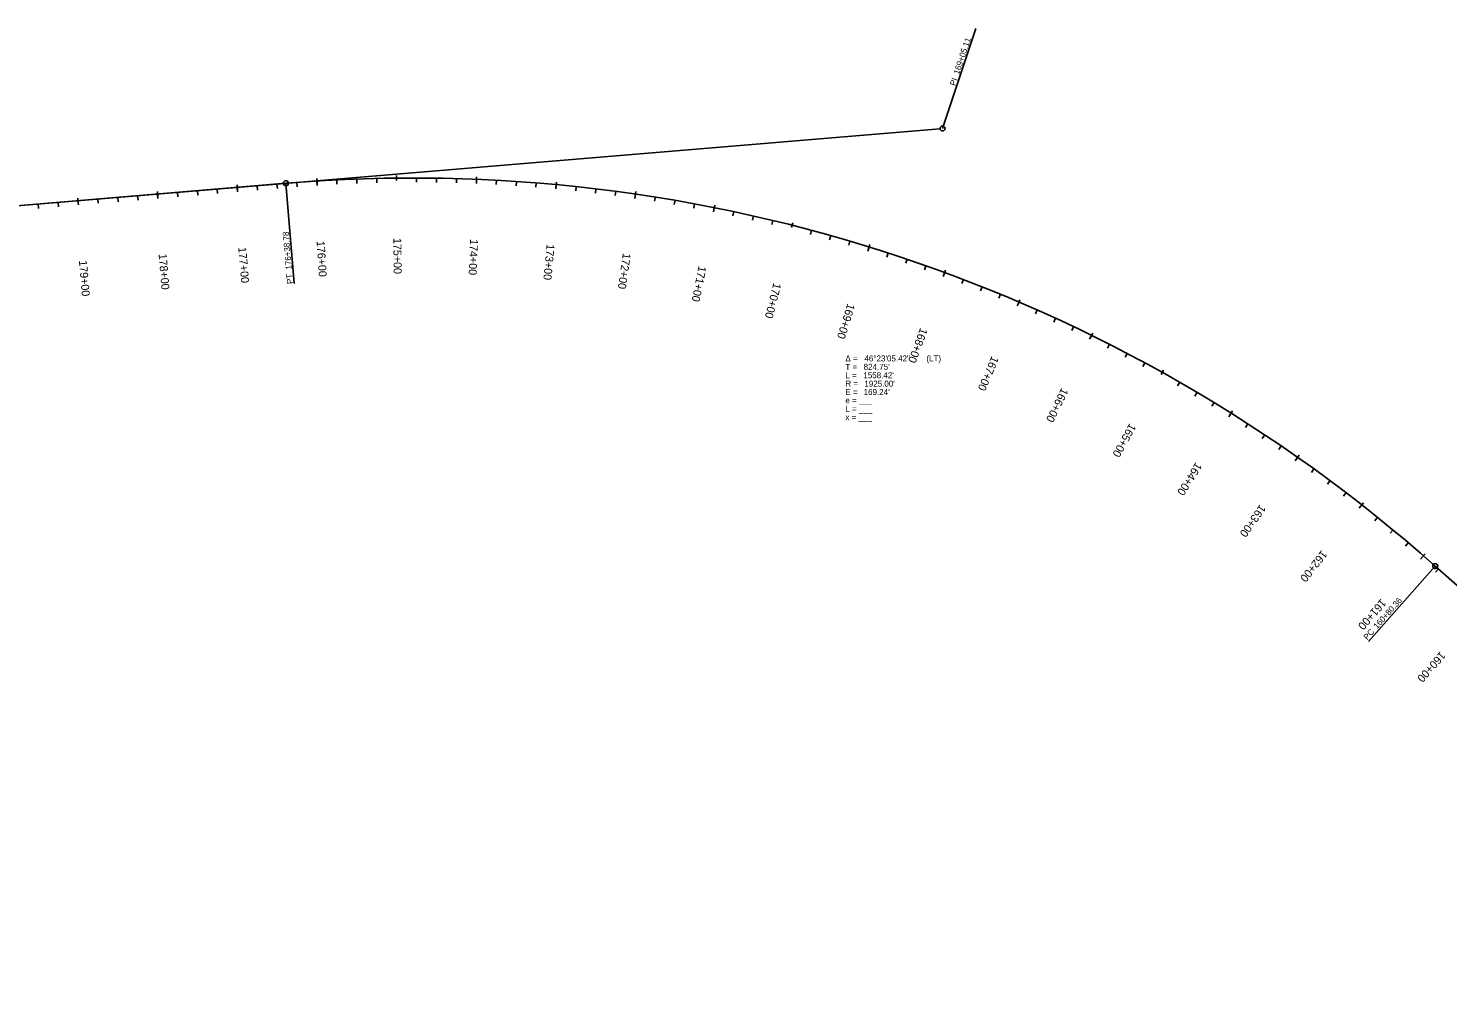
# Model space of a CAD drawing. Extents: x 5226274 to 5237131, y 3641705 to 3648830.
# Drawn here: x 5230736 to 5232512, y 3645314 to 3646508 of the extents above; entities that cross this region are included whole.
import ezdxf

# ---------------------------------------------------------------- set-up
doc = ezdxf.new("R2010")
doc.units = 0
for name, color, linetype in [('Alignment', 7, 'Continuous'), ('TextAlignment', 7, 'Continuous'), ('TextAlignmentLrg', 7, 'Continuous'), ('TextAlignmentSml', 7, 'Continuous')]:
    doc.layers.add(name, color=color, linetype=linetype)

msp = doc.modelspace()

# ---------------------------------------------------------------- linework, layer by layer
at = {"layer": 'Alignment'}
for p, q in [((5231876.8, 3646382.3), (5230085.3, 3646232.7)), ((5231058.4, 3646314), (5230044.9, 3646229.3)), ((5237043, 3641797.1), (5232496.9, 3645834.9))]:
    msp.add_line(p, q, dxfattribs=at)
msp.add_arc((5231218.6, 3644395.6), 1925, 48.3884, 94.7733, dxfattribs=at)
msp.add_arc((5231218.6, 3644395.6), 1925, 48.3884, 94.7733, dxfattribs=at)
at = {"layer": 'TextAlignment'}
for p, q in [((5231880.3, 3646382.6), (5231922, 3646507.8)), ((5231922, 3646507.8), (5231922, 3646507.8)), ((5231058.4, 3646314), (5231068.9, 3646188.4)), ((5231068.9, 3646188.4), (5231068.9, 3646188.4)), ((5232496.9, 3645834.9), (5232413.3, 3645740.7)), ((5232413.3, 3645740.7), (5232413.3, 3645740.7))]:
    msp.add_line(p, q, dxfattribs=at)
for centre in [(5231880.3, 3646382.6), (5231058.4, 3646314), (5232496.9, 3645834.9)]:
    msp.add_circle(centre, 3.12, dxfattribs=at)
at = {"layer": 'TextAlignmentLrg'}
for p, q in [((5230997.4, 3646308.9), (5230997.9, 3646303.4)), ((5231097.1, 3646316.8), (5231097.4, 3646311.4)), ((5231197, 3646317.5), (5231197, 3646323.6)), ((5231297, 3646319), (5231296.8, 3646313.6)), ((5231396.8, 3646312.4), (5231396.2, 3646306.9)), ((5230798.1, 3646292.2), (5230798.6, 3646286.8)), ((5230897.8, 3646300.5), (5230898.2, 3646295.1)), ((5231496, 3646300.5), (5231495.3, 3646295.1)), ((5231594.6, 3646283.6), (5231593.5, 3646278.2)), ((5231691.3, 3646258.5), (5231692.9, 3646264.5)), ((5231788.3, 3646234.4), (5231786.7, 3646229.2)), ((5231883.1, 3646202.3), (5231881.2, 3646197.2)), ((5231976, 3646165.4), (5231973.8, 3646160.4)), ((5232066.8, 3646123.7), (5232064.4, 3646118.8)), ((5232153.9, 3646074.6), (5232156.9, 3646080)), ((5232241.5, 3646026.4), (5232238.6, 3646021.8)), ((5232324.8, 3645971.1), (5232321.6, 3645966.6)), ((5232405.1, 3645911.5), (5232401.7, 3645907.2)), ((5232482.2, 3645847.9), (5232478.6, 3645843.7))]:
    msp.add_line(p, q, dxfattribs=at)
at = {"layer": 'TextAlignmentSml'}
for p, q in [((5230997.7, 3646305.8), (5230997.2, 3646311.9)), ((5231022.3, 3646310.9), (5231022.8, 3646305.5)), ((5231047.2, 3646313), (5231047.7, 3646307.6)), ((5231072.1, 3646315.1), (5231072.6, 3646309.6)), ((5231097.3, 3646313.7), (5231096.9, 3646319.9)), ((5231122, 3646318.2), (5231122.3, 3646312.8)), ((5231147, 3646319.3), (5231147.2, 3646313.9)), ((5231172, 3646320.1), (5231172.1, 3646314.6)), ((5231197, 3646317.5), (5231197, 3646323.6)), ((5231222, 3646320.6), (5231222, 3646315.2)), ((5231247, 3646320.4), (5231246.9, 3646315)), ((5231272, 3646319.9), (5231271.8, 3646314.4)), ((5231296.9, 3646316), (5231297.1, 3646322.1)), ((5231322, 3646317.9), (5231321.7, 3646312.4)), ((5231346.9, 3646316.4), (5231346.5, 3646310.9)), ((5231371.8, 3646314.5), (5231371.4, 3646309.1)), ((5231396.5, 3646309.3), (5231397, 3646315.4)), ((5231421.6, 3646309.9), (5231421.1, 3646304.5)), ((5230773.2, 3646290.1), (5230773.6, 3646284.7)), ((5230798.4, 3646289.2), (5230797.8, 3646295.3)), ((5230823, 3646294.3), (5230823.5, 3646288.9)), ((5230847.9, 3646296.4), (5230848.4, 3646290.9)), ((5230872.8, 3646298.5), (5230873.3, 3646293)), ((5230898, 3646297.5), (5230897.5, 3646303.6)), ((5230922.7, 3646302.6), (5230923.1, 3646297.2)), ((5230947.6, 3646304.7), (5230948, 3646299.3)), ((5230972.5, 3646306.8), (5230972.9, 3646301.3)), ((5231446.5, 3646307.1), (5231445.8, 3646301.7)), ((5231471.3, 3646304), (5231470.6, 3646298.6)), ((5231495.6, 3646297.5), (5231496.5, 3646303.6)), ((5231520.8, 3646296.8), (5231519.9, 3646291.4)), ((5231545.4, 3646292.7), (5231544.5, 3646287.3)), ((5230748.3, 3646288.1), (5230748.7, 3646282.6)), ((5231570, 3646288.3), (5231569, 3646282.9)), ((5231594, 3646280.6), (5231595.2, 3646286.6)), ((5231619.1, 3646278.5), (5231617.9, 3646273.2)), ((5231643.5, 3646273.2), (5231642.3, 3646267.8)), ((5231667.8, 3646267.5), (5231666.6, 3646262.2)), ((5231691.3, 3646258.5), (5231692.9, 3646264.5)), ((5231716.3, 3646255.2), (5231714.9, 3646249.9)), ((5231740.4, 3646248.6), (5231738.9, 3646243.3)), ((5231764.4, 3646241.6), (5231762.9, 3646236.4)), ((5231787.4, 3646231.5), (5231789.2, 3646237.3)), ((5231812.2, 3646226.8), (5231810.5, 3646221.6)), ((5231835.9, 3646219), (5231834.2, 3646213.8)), ((5231859.5, 3646210.8), (5231857.7, 3646205.7)), ((5231882, 3646199.5), (5231884.1, 3646205.2)), ((5231906.5, 3646193.5), (5231904.5, 3646188.4)), ((5231929.7, 3646184.5), (5231927.7, 3646179.4)), ((5231952.9, 3646175.1), (5231950.8, 3646170)), ((5231974.8, 3646162.6), (5231977.2, 3646168.2)), ((5231998.9, 3646155.4), (5231996.7, 3646150.4)), ((5232021.7, 3646145.1), (5232019.4, 3646140.2)), ((5232044.3, 3646134.5), (5232042, 3646129.6)), ((5232065.5, 3646120.9), (5232068.2, 3646126.4)), ((5232089.2, 3646112.5), (5232086.7, 3646107.6)), ((5232111.4, 3646101.1), (5232108.9, 3646096.2)), ((5232133.5, 3646089.3), (5232130.9, 3646084.5)), ((5232153.9, 3646074.6), (5232156.9, 3646080)), ((5232177.2, 3646065), (5232174.5, 3646060.3)), ((5232198.8, 3646052.4), (5232196, 3646047.7)), ((5232220.2, 3646039.5), (5232217.4, 3646034.9)), ((5232239.9, 3646023.8), (5232243.1, 3646029)), ((5232262.6, 3646013), (5232259.6, 3646008.4)), ((5232283.5, 3645999.3), (5232280.5, 3645994.7)), ((5232304.2, 3645985.3), (5232301.1, 3645980.8)), ((5232323, 3645968.6), (5232326.5, 3645973.6)), ((5232345.1, 3645956.6), (5232341.9, 3645952.2)), ((5232365.3, 3645941.8), (5232362.1, 3645937.4)), ((5232385.3, 3645926.8), (5232382, 3645922.5)), ((5232403.2, 3645909.1), (5232407, 3645913.9)), ((5232424.7, 3645896), (5232421.3, 3645891.7)), ((5232444.1, 3645880.2), (5232440.6, 3645876)), ((5232463.2, 3645864.1), (5232459.7, 3645860)), ((5232480.2, 3645845.6), (5232484.2, 3645850.2)), ((5232501, 3645831.3), (5232497.3, 3645827.3))]:
    msp.add_line(p, q, dxfattribs=at)

# ---------------------------------------------------------------- texts
at = {"layer": 'TextAlignment'}
for s, rotation, p in [('169+05.11', 71.5809, (5231900.9, 3646449.6)), ('PI ', 71.5809, (5231896.2, 3646435.4)), ('176+38.78', 94.7733, (5231065.8, 3646206.3)), ('PT', 94.7733, (5231067.3, 3646188.3)), ('160+80.36', 48.3884, (5232424.4, 3645755.7)), ('PC', 48.3884, (5232412, 3645741.8))]:
    msp.add_text(s, height=7.5, rotation=rotation, dxfattribs=at).set_placement(p)
for s, p in [('Δ = ', (5231758.7, 3646091)), ('46°23\'05.42"', (5231782.5, 3646091)), (' (LT)', (5231857.3, 3646091)), ('T = ', (5231758.7, 3646080.5)), ('L = ', (5231758.7, 3646070)), ("1558.42'", (5231781.1, 3646070)), ("824.75'", (5231781.5, 3646080.5)), ('R = ', (5231758.7, 3646059.5)), ("1925.00'", (5231782.4, 3646059.5)), ('e = ___ ', (5231758.7, 3646038.5)), ('E = ', (5231758.7, 3646049)), ("169.24'", (5231781.5, 3646049)), ('x = ___', (5231758.7, 3646017.5)), ('L = ___', (5231758.7, 3646028))]:
    msp.add_text(s, height=7.5, dxfattribs=at).set_placement(p)
at = {"layer": 'TextAlignmentLrg'}
for s, rotation, p in [('175+00', 270.6427, (5231192.8, 3646245.5)), ('170+00', 255.7607, (5231668.8, 3646190)), ('165+00', 240.8787, (5232114.5, 3646014.2)), ('160+00', 228.3884, (5232503.5, 3645728.8))]:
    msp.add_text(s, height=10.02, rotation=rotation, dxfattribs=at).set_placement(p)
at = {"layer": 'TextAlignmentSml'}
for s, rotation, p in [('176+00', 273.6191, (5231096.8, 3646241.6)), ('175+00', 270.6427, (5231192.8, 3646245.5)), ('174+00', 267.6663, (5231288.9, 3646244.3)), ('173+00', 264.6899, (5231384.8, 3646238.2)), ('178+00', 274.7733, (5230899, 3646225.4)), ('177+00', 274.7733, (5230998.7, 3646233.7)), ('172+00', 261.7135, (5231480.3, 3646227)), ('179+00', 274.7733, (5230799.3, 3646217.1)), ('171+00', 258.7371, (5231575, 3646211)), ('170+00', 255.7607, (5231668.8, 3646190)), ('169+00', 252.7843, (5231761.4, 3646164.2)), ('168+00', 249.8079, (5231852.5, 3646133.7)), ('167+00', 246.8315, (5231941.9, 3646098.4)), ('166+00', 243.8551, (5232029.3, 3646058.6)), ('165+00', 240.8787, (5232114.5, 3646014.2)), ('164+00', 237.9022, (5232197.4, 3645965.5)), ('163+00', 234.9258, (5232277.6, 3645912.6)), ('162+00', 231.9494, (5232354.9, 3645855.5)), ('161+00', 228.973, (5232429.2, 3645794.6)), ('160+00', 228.3884, (5232503.5, 3645728.8))]:
    msp.add_text(s, height=10.02, rotation=rotation, dxfattribs=at).set_placement(p)

doc.saveas('drawing.dxf')
